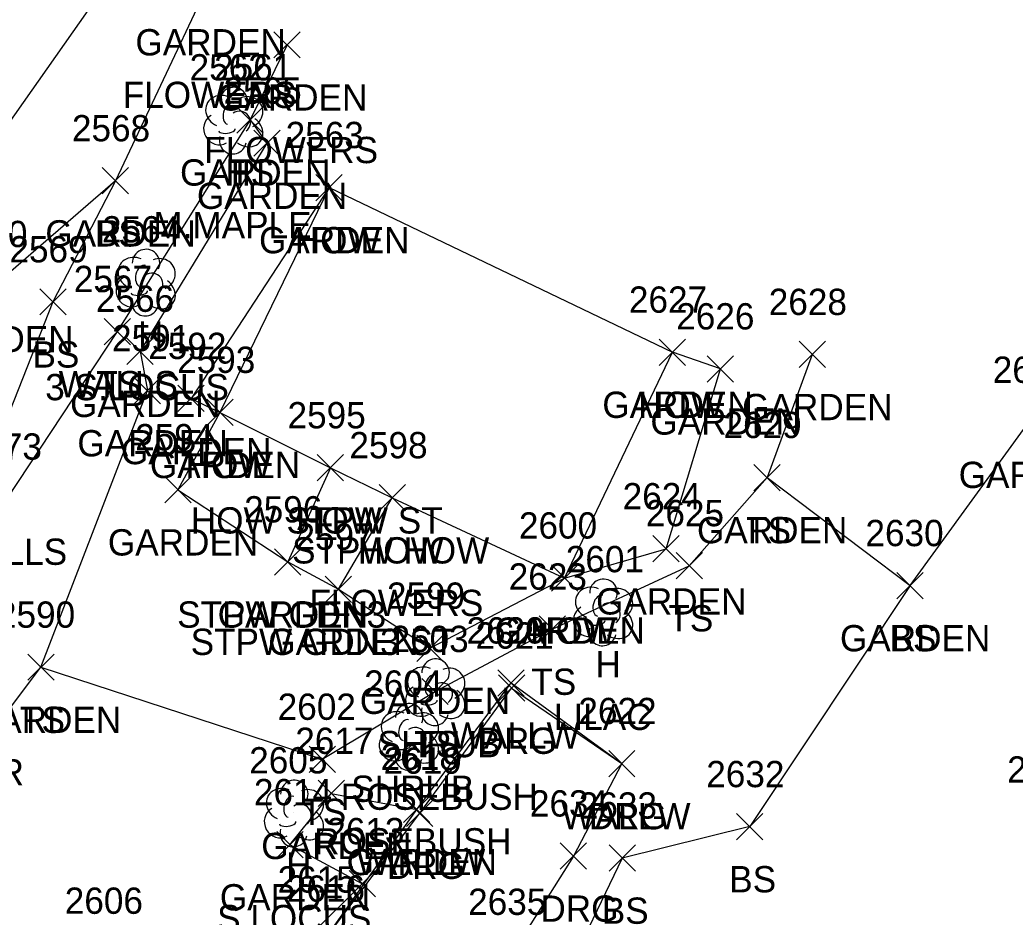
# Model space of a CAD drawing. Extents: x 1499292 to 1501024, y 534584 to 538043.
# Drawn here: x 1499592.5 to 1499668.2, y 537877.8 to 537946 of the extents above; entities that cross this region are included whole.
import ezdxf

# ---------------------------------------------------------------- set-up
doc = ezdxf.new("R2010")
doc.units = 0
for name, color, linetype in [('L_A', 7, 'Continuous'), ('L_C', 7, 'Continuous'), ('L_I', 7, 'Continuous'), ('L_TIC', 7, 'Continuous'), ('LAPB', 7, 'Continuous'), ('LBC', 7, 'Continuous'), ('LBF', 7, 'Continuous'), ('LELB', 7, 'Continuous'), ('LSH', 7, 'Continuous'), ('LTD', 7, 'Continuous'), ('LW', 7, 'Continuous'), ('LWS', 7, 'Continuous'), ('R_A', 7, 'Continuous'), ('R_I', 7, 'Continuous'), ('R_TIC', 7, 'Continuous'), ('RDG', 7, 'Continuous')]:
    doc.layers.add(name, color=color, linetype=linetype)

msp = doc.modelspace()

# ---------------------------------------------------------------- linework, layer by layer
at = {"layer": 'L_TIC'}
for points in [[(1499611.835, 537943.143), (1499613.835, 537945.143)], [(1499613.835, 537943.143), (1499611.835, 537945.143)], [(1499609.023, 537937.433), (1499611.023, 537939.433)], [(1499611.023, 537937.433), (1499609.023, 537939.433)], [(1499609.023, 537937.433), (1499611.023, 537939.433)], [(1499611.023, 537937.433), (1499609.023, 537939.433)], [(1499610.306, 537935.662), (1499612.306, 537937.662)], [(1499612.306, 537935.662), (1499610.306, 537937.662)], [(1499598.775, 537932.802), (1499600.775, 537934.802)], [(1499600.775, 537932.802), (1499598.775, 537934.802)], [(1499598.775, 537932.802), (1499600.775, 537934.802)], [(1499600.775, 537932.802), (1499598.775, 537934.802)], [(1499615.034, 537932.285), (1499617.034, 537934.285)], [(1499617.034, 537932.285), (1499615.034, 537934.285)], [(1499615.034, 537932.285), (1499617.034, 537934.285)], [(1499617.034, 537932.285), (1499615.034, 537934.285)], [(1499615.034, 537932.285), (1499617.034, 537934.285)], [(1499617.034, 537932.285), (1499615.034, 537934.285)], [(1499594.027, 537923.594), (1499596.027, 537925.594)], [(1499596.027, 537923.594), (1499594.027, 537925.594)], [(1499598.915, 537921.334), (1499600.915, 537923.334)], [(1499600.915, 537921.334), (1499598.915, 537923.334)], [(1499598.915, 537921.334), (1499600.915, 537923.334)], [(1499600.915, 537921.334), (1499598.915, 537923.334)], [(1499600.656, 537919.831), (1499602.656, 537921.831)], [(1499602.656, 537919.831), (1499600.656, 537921.831)], [(1499641.152, 537919.764), (1499643.152, 537921.764)], [(1499643.152, 537919.764), (1499641.152, 537921.764)], [(1499641.152, 537919.764), (1499643.152, 537921.764)], [(1499643.152, 537919.764), (1499641.152, 537921.764)], [(1499641.152, 537919.764), (1499643.152, 537921.764)], [(1499643.152, 537919.764), (1499641.152, 537921.764)], [(1499651.79, 537919.591), (1499653.79, 537921.591)], [(1499653.79, 537919.591), (1499651.79, 537921.591)], [(1499644.808, 537918.492), (1499646.808, 537920.492)], [(1499646.808, 537918.492), (1499644.808, 537920.492)], [(1499601.213, 537916.838), (1499603.213, 537918.838)], [(1499603.213, 537916.838), (1499601.213, 537918.838)], [(1499601.213, 537916.838), (1499603.213, 537918.838)], [(1499603.213, 537916.838), (1499601.213, 537918.838)], [(1499604.534, 537916.244), (1499606.534, 537918.244)], [(1499606.534, 537916.244), (1499604.534, 537918.244)], [(1499606.729, 537915.186), (1499608.729, 537917.186)], [(1499608.729, 537915.186), (1499606.729, 537917.186)], [(1499606.729, 537915.186), (1499608.729, 537917.186)], [(1499608.729, 537915.186), (1499606.729, 537917.186)], [(1499615.132, 537910.971), (1499617.132, 537912.971)], [(1499617.132, 537910.971), (1499615.132, 537912.971)], [(1499615.132, 537910.971), (1499617.132, 537912.971)], [(1499617.132, 537910.971), (1499615.132, 537912.971)], [(1499648.353, 537910.231), (1499650.353, 537912.231)], [(1499650.353, 537910.231), (1499648.353, 537912.231)], [(1499648.353, 537910.231), (1499650.353, 537912.231)], [(1499650.353, 537910.231), (1499648.353, 537912.231)], [(1499603.532, 537909.299), (1499605.532, 537911.299)], [(1499605.532, 537909.299), (1499603.532, 537911.299)], [(1499619.838, 537908.691), (1499621.838, 537910.691)], [(1499621.838, 537908.691), (1499619.838, 537910.691)], [(1499619.838, 537908.691), (1499621.838, 537910.691)], [(1499621.838, 537908.691), (1499619.838, 537910.691)], [(1499640.675, 537904.811), (1499642.675, 537906.811)], [(1499642.675, 537904.811), (1499640.675, 537906.811)], [(1499611.884, 537903.812), (1499613.884, 537905.812)], [(1499613.884, 537903.812), (1499611.884, 537905.812)], [(1499611.884, 537903.812), (1499613.884, 537905.812)], [(1499613.884, 537903.812), (1499611.884, 537905.812)], [(1499642.438, 537903.526), (1499644.438, 537905.526)], [(1499644.438, 537903.526), (1499642.438, 537905.526)], [(1499632.948, 537902.586), (1499634.948, 537904.586)], [(1499634.948, 537902.586), (1499632.948, 537904.586)], [(1499632.948, 537902.586), (1499634.948, 537904.586)], [(1499634.948, 537902.586), (1499632.948, 537904.586)], [(1499659.231, 537902.009), (1499661.231, 537904.009)], [(1499661.231, 537902.009), (1499659.231, 537904.009)], [(1499659.231, 537902.009), (1499661.231, 537904.009)], [(1499661.231, 537902.009), (1499659.231, 537904.009)], [(1499615.737, 537901.734), (1499617.737, 537903.734)], [(1499617.737, 537901.734), (1499615.737, 537903.734)], [(1499615.737, 537901.734), (1499617.737, 537903.734)], [(1499617.737, 537901.734), (1499615.737, 537903.734)], [(1499632.007, 537898.7), (1499634.007, 537900.7)], [(1499634.007, 537898.7), (1499632.007, 537900.7)], [(1499622.7, 537897.247), (1499624.7, 537899.247)], [(1499624.7, 537897.247), (1499622.7, 537899.247)], [(1499593.11, 537895.805), (1499595.11, 537897.805)], [(1499595.11, 537895.805), (1499593.11, 537897.805)], [(1499593.11, 537895.805), (1499595.11, 537897.805)], [(1499595.11, 537895.805), (1499593.11, 537897.805)], [(1499628.881, 537894.602), (1499630.881, 537896.602)], [(1499630.881, 537894.602), (1499628.881, 537896.602)], [(1499623.092, 537893.954), (1499625.092, 537895.954)], [(1499625.092, 537893.954), (1499623.092, 537895.954)], [(1499614.509, 537888.798), (1499616.509, 537890.798)], [(1499616.509, 537888.798), (1499614.509, 537890.798)], [(1499637.306, 537888.471), (1499639.306, 537890.471)], [(1499639.306, 537888.471), (1499637.306, 537890.471)], [(1499615.201, 537886.207), (1499617.201, 537888.207)], [(1499617.201, 537886.207), (1499615.201, 537888.207)], [(1499621.698, 537884.986), (1499623.698, 537886.986)], [(1499623.698, 537884.986), (1499621.698, 537886.986)], [(1499621.698, 537884.986), (1499623.698, 537886.986)], [(1499623.698, 537884.986), (1499621.698, 537886.986)], [(1499647.036, 537883.677), (1499649.036, 537885.677)], [(1499649.036, 537883.677), (1499647.036, 537885.677)], [(1499612.052, 537882.301), (1499614.052, 537884.301)], [(1499614.052, 537882.301), (1499612.052, 537884.301)], [(1499637.338, 537881.285), (1499639.338, 537883.285)], [(1499639.338, 537881.285), (1499637.338, 537883.285)], [(1499617.556, 537879.336), (1499619.556, 537881.336)], [(1499619.556, 537879.336), (1499617.556, 537881.336)], [(1499617.556, 537879.336), (1499619.556, 537881.336)], [(1499619.556, 537879.336), (1499617.556, 537881.336)]]:
    msp.add_lwpolyline(points, dxfattribs=at)
at = {"layer": 'LAPB'}
for points in [[(1499606.629, 537948.337), (1499599.775, 537933.802), (1499590.485, 537925.756), (1499582.838, 537910.985), (1499582.072, 537908.689), (1499576.215, 537894.586), (1499577.703, 537881.508), (1499584.328, 537880.125), (1499585.633, 537885.562), (1499594.11, 537896.805), (1499602.213, 537917.838)], [(1499612.835, 537944.143), (1499610.023, 537938.433), (1499611.306, 537936.662), (1499601.656, 537920.831), (1499602.213, 537917.838)], [(1499616.034, 537933.285), (1499605.534, 537917.244), (1499607.729, 537916.186), (1499604.532, 537910.299), (1499612.884, 537904.812)], [(1499616.737, 537902.734), (1499623.7, 537898.247), (1499633.948, 537903.586), (1499641.675, 537905.811), (1499645.808, 537919.492), (1499642.152, 537920.764)], [(1499652.79, 537920.591), (1499649.353, 537911.231), (1499660.231, 537903.009), (1499669.265, 537915.432)], [(1499618.556, 537880.336), (1499613.052, 537883.301), (1499616.201, 537887.207), (1499622.698, 537885.986)]]:
    msp.add_lwpolyline(points, dxfattribs=at)
at = {"layer": 'LBC'}
for points in [[(1499616.034, 537933.285), (1499607.729, 537916.186), (1499616.132, 537911.971), (1499620.838, 537909.691), (1499633.948, 537903.586), (1499642.152, 537920.764)], [(1499616.034, 537933.285), (1499642.152, 537920.764)]]:
    msp.add_lwpolyline(points, dxfattribs=at)
at = {"layer": 'LBF'}
msp.add_lwpolyline([(1499616.132, 537911.971), (1499612.884, 537904.812), (1499616.737, 537902.734), (1499620.838, 537909.691)], dxfattribs=at)
at = {"layer": 'LELB'}
for points in [[(1499610.023, 537938.433), (1499599.915, 537922.334)], [(1499599.775, 537933.802), (1499595.027, 537924.594), (1499588.775, 537908.82)], [(1499594.11, 537896.805), (1499615.509, 537889.798), (1499624.092, 537894.954), (1499633.007, 537899.7), (1499643.438, 537904.526), (1499649.353, 537911.231)], [(1499660.231, 537903.009), (1499648.036, 537884.677), (1499638.338, 537882.285), (1499632.925, 537871.051)]]:
    msp.add_lwpolyline(points, dxfattribs=at)
at = {"layer": 'LSH'}
for p, q in [((1499624.092, 537894.954), (1499624.092, 537894.954)), ((1499624.092, 537894.954), (1499624.092, 537894.954)), ((1499622.086, 537891.559), (1499622.086, 537891.559)), ((1499622.086, 537891.559), (1499622.086, 537891.559))]:
    msp.add_line(p, q, dxfattribs=at)
for centre in [(1499624.138, 537896.388), (1499622.133, 537892.993)]:
    msp.add_arc(centre, 1.047, 335.52715, 180.95627, dxfattribs=at)
for centre, major_axis, ratio, start_param, end_param in [((1499623.3, 537895.621), (1.21, -0.512), 0.895232, 1.570796, 4.712389), ((1499625.133, 537895.538), (-1.141, -0.483), 0.949671, 1.570796, 4.712389), ((1499623.883, 537895.412), (-0.208, -0.792), 0.645439, 3.141593, 6.283185), ((1499624.592, 537894.787), (-0.5, 0.667), 0.989748, 3.141593, 6.283185), ((1499623.008, 537894.246), (0.584, -1.042), 0.959034, 3.141593, 6.283185), ((1499625.092, 537894.121), (-1.09, 0.792), 0.841452, 1.570796, 4.712389), ((1499623.633, 537894.204), (-0.625, -0.083), 0.423636, 0, 3.141593), ((1499621.295, 537892.225), (1.21, -0.512), 0.895232, 1.570796, 4.712389), ((1499623.128, 537892.142), (-1.141, -0.483), 0.949671, 1.570796, 4.712389), ((1499624.092, 537893.454), (0.265, 1.061), 0.942809, 1.570796, 4.712389), ((1499621.878, 537892.017), (-0.208, -0.792), 0.645439, 3.141593, 6.283185), ((1499621.003, 537890.85), (0.584, -1.042), 0.959034, 3.141593, 6.283185), ((1499622.586, 537891.392), (-0.5, 0.667), 0.989748, 3.141593, 6.283185), ((1499623.086, 537890.726), (-1.09, 0.792), 0.841452, 1.570796, 4.712389), ((1499622.087, 537890.059), (0.265, 1.061), 0.942809, 1.570796, 4.712389), ((1499621.628, 537890.809), (-0.625, -0.083), 0.423636, 0, 3.141593)]:
    msp.add_ellipse(centre, major_axis=major_axis, ratio=ratio, start_param=start_param, end_param=end_param, dxfattribs=at)
at = {"layer": 'LTD'}
for p, q in [((1499608.725, 537938.432), (1499608.725, 537938.432)), ((1499608.725, 537938.432), (1499608.725, 537938.432)), ((1499602.059, 537926.11), (1499602.059, 537926.11)), ((1499602.059, 537926.11), (1499602.059, 537926.11)), ((1499636.861, 537901.025), (1499636.861, 537901.025)), ((1499636.861, 537901.025), (1499636.861, 537901.025)), ((1499613.34, 537885.722), (1499613.34, 537885.722)), ((1499613.34, 537885.722), (1499613.34, 537885.722))]:
    msp.add_line(p, q, dxfattribs=at)
for centre in [(1499608.772, 537939.866), (1499602.106, 537927.544), (1499636.907, 537902.459), (1499613.387, 537887.156)]:
    msp.add_arc(centre, 1.047, 335.52715, 180.95627, dxfattribs=at)
for centre, major_axis, ratio, start_param, end_param in [((1499607.933, 537939.099), (1.21, -0.512), 0.895232, 1.570796, 4.712389), ((1499609.766, 537939.016), (-1.141, -0.483), 0.949671, 1.570796, 4.712389), ((1499608.516, 537938.89), (-0.208, -0.792), 0.645439, 3.141593, 6.283185), ((1499607.642, 537937.723), (0.584, -1.042), 0.959034, 3.141593, 6.283185), ((1499609.225, 537938.265), (-0.5, 0.667), 0.989748, 3.141593, 6.283185), ((1499609.725, 537937.599), (-1.09, 0.792), 0.841452, 1.570796, 4.712389), ((1499608.267, 537937.682), (-0.625, -0.083), 0.423636, 0, 3.141593), ((1499608.725, 537936.932), (0.265, 1.061), 0.942809, 1.570796, 4.712389), ((1499601.268, 537926.777), (1.21, -0.512), 0.895232, 1.570796, 4.712389), ((1499601.851, 537926.568), (-0.208, -0.792), 0.645439, 3.141593, 6.283185), ((1499603.101, 537926.694), (-1.141, -0.483), 0.949671, 1.570796, 4.712389), ((1499602.559, 537925.943), (-0.5, 0.667), 0.989748, 3.141593, 6.283185), ((1499600.976, 537925.401), (0.584, -1.042), 0.959034, 3.141593, 6.283185), ((1499603.06, 537925.277), (-1.09, 0.792), 0.841452, 1.570796, 4.712389), ((1499601.601, 537925.36), (-0.625, -0.083), 0.423636, 0, 3.141593), ((1499602.06, 537924.61), (0.265, 1.061), 0.942809, 1.570796, 4.712389), ((1499636.069, 537901.691), (1.21, -0.512), 0.895232, 1.570796, 4.712389), ((1499637.902, 537901.608), (-1.141, -0.483), 0.949671, 1.570796, 4.712389), ((1499636.652, 537901.483), (-0.208, -0.792), 0.645439, 3.141593, 6.283185), ((1499637.361, 537900.858), (-0.5, 0.667), 0.989748, 3.141593, 6.283185), ((1499635.777, 537900.316), (0.584, -1.042), 0.959034, 3.141593, 6.283185), ((1499637.861, 537900.192), (-1.09, 0.792), 0.841452, 1.570796, 4.712389), ((1499636.402, 537900.275), (-0.625, -0.083), 0.423636, 0, 3.141593), ((1499636.861, 537899.525), (0.265, 1.061), 0.942809, 1.570796, 4.712389), ((1499612.549, 537886.388), (1.21, -0.512), 0.895232, 1.570796, 4.712389), ((1499614.382, 537886.305), (-1.141, -0.483), 0.949671, 1.570796, 4.712389), ((1499613.132, 537886.18), (-0.208, -0.792), 0.645439, 3.141593, 6.283185), ((1499612.257, 537885.013), (0.584, -1.042), 0.959034, 3.141593, 6.283185), ((1499613.84, 537885.555), (-0.5, 0.667), 0.989748, 3.141593, 6.283185), ((1499614.34, 537884.889), (-1.09, 0.792), 0.841452, 1.570796, 4.712389), ((1499612.882, 537884.972), (-0.625, -0.083), 0.423636, 0, 3.141593), ((1499613.341, 537884.222), (0.265, 1.061), 0.942809, 1.570796, 4.712389)]:
    msp.add_ellipse(centre, major_axis=major_axis, ratio=ratio, start_param=start_param, end_param=end_param, dxfattribs=at)
at = {"layer": 'LW'}
msp.add_lwpolyline([(1499618.556, 537880.336), (1499614.859, 537876.659), (1499615.61, 537875.966), (1499622.698, 537885.986), (1499629.881, 537895.602), (1499638.306, 537889.471)], dxfattribs=at)
at = {"layer": 'LWS'}
msp.add_lwpolyline([(1499599.915, 537922.334), (1499591.493, 537909.589), (1499586.43, 537896.83), (1499583.679, 537893.415), (1499581.68, 537890.308)], dxfattribs=at)
at = {"layer": 'R_TIC'}
for points in [[(1499628.918, 537894.211), (1499630.918, 537896.211)], [(1499630.918, 537894.211), (1499628.918, 537896.211)], [(1499637.306, 537888.471), (1499639.306, 537890.471)], [(1499639.306, 537888.471), (1499637.306, 537890.471)], [(1499621.932, 537884.698), (1499623.932, 537886.698)], [(1499623.932, 537884.698), (1499621.932, 537886.698)], [(1499633.617, 537881.442), (1499635.617, 537883.442)], [(1499635.617, 537881.442), (1499633.617, 537883.442)]]:
    msp.add_lwpolyline(points, dxfattribs=at)
at = {"layer": 'RDG'}
for points in [[(1499601.461, 537952.146), (1499588.944, 537934.387), (1499579.82, 537914.693), (1499572.487, 537900.312), (1499566.448, 537888.249), (1499565.054, 537884.662)], [(1499606.958, 537860.671), (1499609.124, 537863.443), (1499614.263, 537870.665), (1499615.61, 537875.966), (1499622.932, 537885.698), (1499629.918, 537895.211), (1499638.306, 537889.471), (1499634.617, 537882.442), (1499629.919, 537874.961), (1499624.289, 537866.6), (1499617.216, 537858.019), (1499615.607, 537855.954)]]:
    msp.add_lwpolyline(points, dxfattribs=at)

# ---------------------------------------------------------------- texts
at = {"layer": 'L_A'}
for s, p in [('GARDEN', (1499601.298, 537943.337)), ('GARDEN', (1499607.504, 537939.143)), ('GARDEN', (1499604.693, 537933.433)), ('H', (1499608.158, 537933.432)), ('TS', (1499608.433, 537933.433)), ('GARDEN', (1499605.976, 537931.662)), ('GARDEN', (1499594.444, 537928.802)), ('BS', (1499598.216, 537928.802)), ('GARDEN', (1499610.704, 537928.285)), ('HOW', (1499613.42, 537928.285)), ('HOW', (1499613.42, 537928.285)), ('H', (1499601.492, 537921.11)), ('GARDEN', (1499585.154, 537920.756)), ('BS', (1499593.468, 537919.594)), ('WALLS', (1499595.458, 537917.334)), ('TS', (1499598.325, 537917.334)), ('GARDEN', (1499596.325, 537915.831)), ('GARDEN', (1499636.821, 537915.764)), ('HOW', (1499639.537, 537915.764)), ('HOW', (1499639.537, 537915.764)), ('GARDEN', (1499647.459, 537915.591)), ('GARDEN', (1499640.477, 537914.492)), ('GARDEN', (1499596.882, 537912.838)), ('GARDEN', (1499596.882, 537912.838)), ('GARDEN', (1499600.203, 537912.244)), ('GARDEN', (1499602.398, 537911.186)), ('HOW', (1499605.115, 537911.186)), ('GARDEN', (1499663.934, 537910.432)), ('HOW STPW ST', (1499605.51, 537906.971)), ('HOW', (1499613.518, 537906.971)), ('GARDEN', (1499644.022, 537906.231)), ('TS', (1499647.762, 537906.231)), ('GARDEN', (1499599.201, 537905.299)), ('WALLS', (1499587.036, 537904.589)), ('STPW HOW', (1499613.216, 537904.691)), ('HOW', (1499618.223, 537904.691)), ('GARDEN', (1499636.344, 537900.811)), ('STPW GDN3', (1499604.475, 537899.812)), ('GARDEN', (1499607.554, 537899.812)), ('TS', (1499641.848, 537899.526)), ('GARDEN', (1499628.617, 537898.586)), ('HOW', (1499631.334, 537898.586)), ('STPW GDN3 ST', (1499605.501, 537897.734)), ('GARDEN', (1499611.407, 537897.734)), ('GARDEN', (1499654.901, 537898.009)), ('BS', (1499658.672, 537898.009)), ('H', (1499636.294, 537896.025)), ('TS', (1499631.417, 537894.7)), ('GARDEN', (1499618.37, 537893.247)), ('GARDEN', (1499588.779, 537891.805)), ('TS', (1499592.52, 537891.805)), ('WALLW', (1499625.298, 537890.602)), ('SHRUB', (1499619.721, 537889.954)), ('TS', (1499622.501, 537889.954)), ('SHRUB', (1499617.716, 537886.559)), ('TS', (1499613.918, 537884.798)), ('WALLW', (1499633.724, 537884.471)), ('GARDEN', (1499610.87, 537882.207)), ('GARDEN', (1499617.367, 537880.986)), ('WALLW', (1499618.115, 537880.986)), ('H', (1499612.773, 537880.722)), ('BS', (1499646.477, 537879.677)), ('GARDEN', (1499607.721, 537878.301)), ('BS', (1499636.779, 537877.285))]:
    msp.add_text(s, height=2, dxfattribs=at).set_placement(p)
at = {"layer": 'L_C'}
for s, p in [('FLOWERS', (1499600.33, 537939.337)), ('FLOWERS', (1499606.536, 537935.143)), ('M.MAPLE', (1499602.662, 537929.432)), ('3 S.LOCUS', (1499594.437, 537917.11)), ('FLOWERS', (1499614.538, 537900.691)), ('LILAC', (1499633.136, 537892.025)), ('M.CEDAR', (1499580.485, 537887.83)), ('ROSEBUSH', (1499616.91, 537885.954)), ('ROSEBUSH', (1499614.905, 537882.559)), ('S.LOCUS', (1499607.514, 537876.722))]:
    msp.add_text(s, height=2, dxfattribs=at).set_placement(p)
at = {"layer": 'L_I'}
for s, p in [('2562', (1499605.418, 537941.432)), ('2561', (1499607.283, 537941.433)), ('2561', (1499607.283, 537941.433)), ('2565', (1499607.999, 537939.662)), ('2568', (1499596.468, 537936.802)), ('2568', (1499596.468, 537936.802)), ('2563', (1499612.727, 537936.285)), ('2563', (1499612.727, 537936.285)), ('2563', (1499612.727, 537936.285)), ('2570', (1499587.138, 537928.756)), ('2564', (1499598.752, 537929.11)), ('2569', (1499591.712, 537927.594)), ('2567', (1499596.608, 537925.334)), ('2567', (1499596.608, 537925.334)), ('2566', (1499598.294, 537923.831)), ('2627', (1499638.844, 537923.764)), ('2627', (1499638.844, 537923.764)), ('2627', (1499638.844, 537923.764)), ('2628', (1499649.483, 537923.591)), ('2626', (1499642.445, 537922.492)), ('2591', (1499599.52, 537920.838)), ('2591', (1499599.52, 537920.838)), ('2592', (1499602.274, 537920.244)), ('2593', (1499604.469, 537919.186)), ('2593', (1499604.469, 537919.186)), ('2631', (1499666.525, 537918.432)), ('2595', (1499612.872, 537914.971)), ('2595', (1499612.872, 537914.971)), ('2629', (1499646.038, 537914.231)), ('2629', (1499646.038, 537914.231)), ('2594', (1499601.272, 537913.299)), ('2573', (1499588.233, 537912.589)), ('2598', (1499617.578, 537912.691)), ('2598', (1499617.578, 537912.691)), ('2624', (1499638.368, 537908.811)), ('2596', (1499609.569, 537907.812)), ('2596', (1499609.569, 537907.812)), ('2625', (1499640.131, 537907.526)), ('2600', (1499630.476, 537906.586)), ('2600', (1499630.476, 537906.586)), ('2597', (1499613.477, 537905.734)), ('2597', (1499613.477, 537905.734)), ('2630', (1499656.838, 537906.009)), ('2630', (1499656.838, 537906.009)), ('2601', (1499634.042, 537904.025)), ('2623', (1499629.7, 537902.7)), ('2599', (1499620.433, 537901.247)), ('2590', (1499590.764, 537899.805)), ('2590', (1499590.764, 537899.805)), ('2620', (1499626.487, 537898.602)), ('2603', (1499620.706, 537897.954)), ('2603', (1499620.706, 537897.954)), ('2604', (1499618.7, 537894.559)), ('2602', (1499612.123, 537892.798)), ('2622', (1499634.999, 537892.471)), ('2617', (1499613.461, 537890.207)), ('2605', (1499609.955, 537888.722)), ('2618', (1499619.958, 537888.986)), ('2618', (1499619.958, 537888.986)), ('2632', (1499644.729, 537887.677)), ('2669', (1499667.624, 537888.024)), ('2614', (1499610.312, 537886.301)), ('2633', (1499635.031, 537885.285)), ('2613', (1499615.816, 537883.336)), ('2613', (1499615.816, 537883.336)), ('2615', (1499612.118, 537879.659)), ('2616', (1499612.814, 537878.966)), ('2606', (1499595.921, 537878.044)), ('2635', (1499626.612, 537877.961))]:
    msp.add_text(s, height=2, dxfattribs=at).set_placement(p)
at = {"layer": 'R_A'}
for p in [(1499627.406, 537890.211), (1499635.795, 537884.471), (1499620.42, 537880.698), (1499632.106, 537877.442)]:
    msp.add_text('DRG', height=2, dxfattribs=at).set_placement(p)
at = {"layer": 'R_I'}
for s, p in [('2621', (1499627.178, 537898.211)), ('2622', (1499634.999, 537892.471)), ('2619', (1499620.184, 537888.698)), ('2634', (1499631.31, 537885.442)), ('2616', (1499612.814, 537878.966)), ('2635', (1499626.612, 537877.961))]:
    msp.add_text(s, height=2, dxfattribs=at).set_placement(p)

doc.saveas('drawing.dxf')
